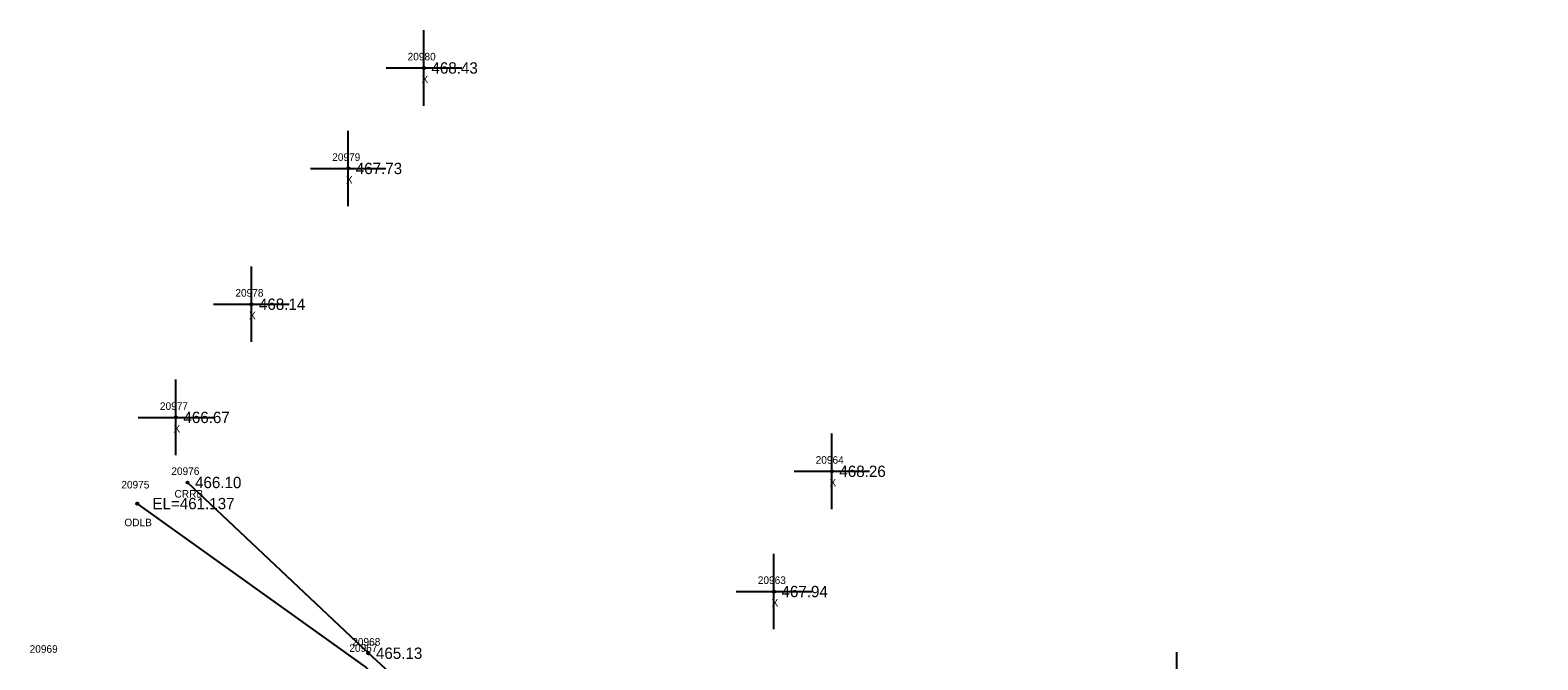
# Model space of a CAD drawing. Extents: x 1741010 to 1742139, y 749382 to 750625.
# Drawn here: x 1741046.9 to 1741246.5, y 750251.1 to 750334.4 of the extents above; entities that cross this region are included whole.
import ezdxf

# ---------------------------------------------------------------- set-up
doc = ezdxf.new("R2010")
doc.units = 0
for name, color, linetype in [('RD_EX_H2O', 7, 'Continuous'), ('RD_EX_H2O_txCode', 7, 'Continuous'), ('RD_EX_Misc', 7, 'Continuous'), ('RD_EX_Misc_txCode', 7, 'Continuous'), ('RD_EX_TX_H2O_ELEV', 7, 'Continuous'), ('RD_EX_TX_Misc_ELEV', 7, 'Continuous'), ('RD_SMD_Locator', 7, 'Continuous')]:
    doc.layers.add(name, color=color, linetype=linetype)

msp = doc.modelspace()

# ---------------------------------------------------------------- linework, layer by layer
at = {"layer": 'RD_EX_H2O'}
for points in [[(1741531.4, 750163.48), (1741496.74, 750161.28), (1741466.68, 750164.86), (1741447.36, 750172.02), (1741386.3, 750192.01), (1741353.76, 750217.14), (1741329.62, 750224.53), (1741303.91, 750221.92), (1741291.61, 750196.83), (1741282.64, 750163.36), (1741273.67, 750156.83), (1741266.54, 750162.04), (1741226.59, 750163.86), (1741212.64, 750167.03), (1741192.26, 750172.18), (1741170.42, 750180.69), (1741154.09, 750191.77), (1741121.46, 750224.58), (1741091.69, 750251.93), (1741067.74, 750274.52)], [(1741529.44, 750151.69), (1741495.88, 750157.28), (1741465.36, 750157.67), (1741446.42, 750166.61), (1741384.48, 750187.47), (1741350.45, 750210.87), (1741329.18, 750218), (1741305.86, 750217.64), (1741298.92, 750196.11), (1741302.53, 750181.39), (1741301.05, 750174.92), (1741291.08, 750166.14), (1741279.91, 750156.54), (1741273.82, 750151.82), (1741263.7, 750152.66), (1741226.75, 750162.85), (1741212.53, 750164.38), (1741190.98, 750170.64), (1741169.63, 750179.08), (1741152.49, 750189.88), (1741119.79, 750222.83), (1741091.32, 750250.11), (1741061.1, 750271.73)]]:
    msp.add_lwpolyline(points, dxfattribs=at)
at = {"layer": 'RD_EX_Misc'}
for p, q in [((1741099.04, 750324.37), (1741099.04, 750334.37)), ((1741094.04, 750329.37), (1741104.04, 750329.37)), ((1741089.02, 750311.07), (1741089.02, 750321.07)), ((1741084.02, 750316.07), (1741094.02, 750316.07)), ((1741076.2, 750293.11), (1741076.2, 750303.11)), ((1741071.2, 750298.11), (1741081.2, 750298.11)), ((1741066.2, 750278.13), (1741066.2, 750288.13)), ((1741061.2, 750283.13), (1741071.2, 750283.13)), ((1741153.04, 750271), (1741153.04, 750281)), ((1741148.04, 750276), (1741158.04, 750276)), ((1741145.38, 750255.09), (1741145.38, 750265.09)), ((1741140.38, 750260.09), (1741150.38, 750260.09)), ((1741198.71, 750242.05), (1741198.71, 750252.05))]:
    msp.add_line(p, q, dxfattribs=at)
at = {"layer": 'RD_SMD_Locator'}
for centre in [(1741099.04, 750329.37), (1741089.02, 750316.07), (1741076.2, 750298.11), (1741066.2, 750283.13), (1741153.04, 750276), (1741067.74, 750274.52), (1741061.1, 750271.73), (1741145.38, 750260.09), (1741091.69, 750251.93)]:
    msp.add_circle(centre, 0.15, dxfattribs=at)

# ---------------------------------------------------------------- texts
at = {"layer": 'RD_EX_H2O_txCode'}
for s, p in [('20975', (1741058.98, 750273.73)), ('20976', (1741065.6, 750275.52)), ('CRRB', (1741066.02, 750272.52)), ('ODLB', (1741059.38, 750268.73)), ('20969', (1741046.84, 750251.99)), ('20967', (1741089.17, 750252.11)), ('20968', (1741089.55, 750252.93))]:
    msp.add_text(s, height=1, dxfattribs=at).set_placement(p)
at = {"layer": 'RD_EX_Misc_txCode'}
for s, p in [('20980', (1741096.88, 750330.37)), ('X', (1741098.72, 750327.37)), ('20979', (1741086.9, 750317.07)), ('X', (1741088.71, 750314.07)), ('20978', (1741074.08, 750299.11)), ('X', (1741075.88, 750296.11)), ('20977', (1741064.09, 750284.13)), ('X', (1741065.89, 750281.13)), ('20964', (1741150.9, 750277)), ('X', (1741152.73, 750274)), ('20963', (1741143.24, 750261.09)), ('X', (1741145.06, 750258.09))]:
    msp.add_text(s, height=1, dxfattribs=at).set_placement(p)
at = {"layer": 'RD_EX_TX_H2O_ELEV'}
for s, p in [('466.10', (1741068.74, 750273.77)), ('EL=461.137', (1741063.1, 750270.98)), ('465.13', (1741092.69, 750251.18))]:
    msp.add_text(s, height=1.5, dxfattribs=at).set_placement(p)
at = {"layer": 'RD_EX_TX_Misc_ELEV'}
for s, p in [('468.43', (1741100.04, 750328.62)), ('467.73', (1741090.02, 750315.32)), ('468.14', (1741077.2, 750297.36)), ('466.67', (1741067.2, 750282.38)), ('468.26', (1741154.04, 750275.25)), ('467.94', (1741146.38, 750259.34))]:
    msp.add_text(s, height=1.5, dxfattribs=at).set_placement(p)

doc.saveas('drawing.dxf')
